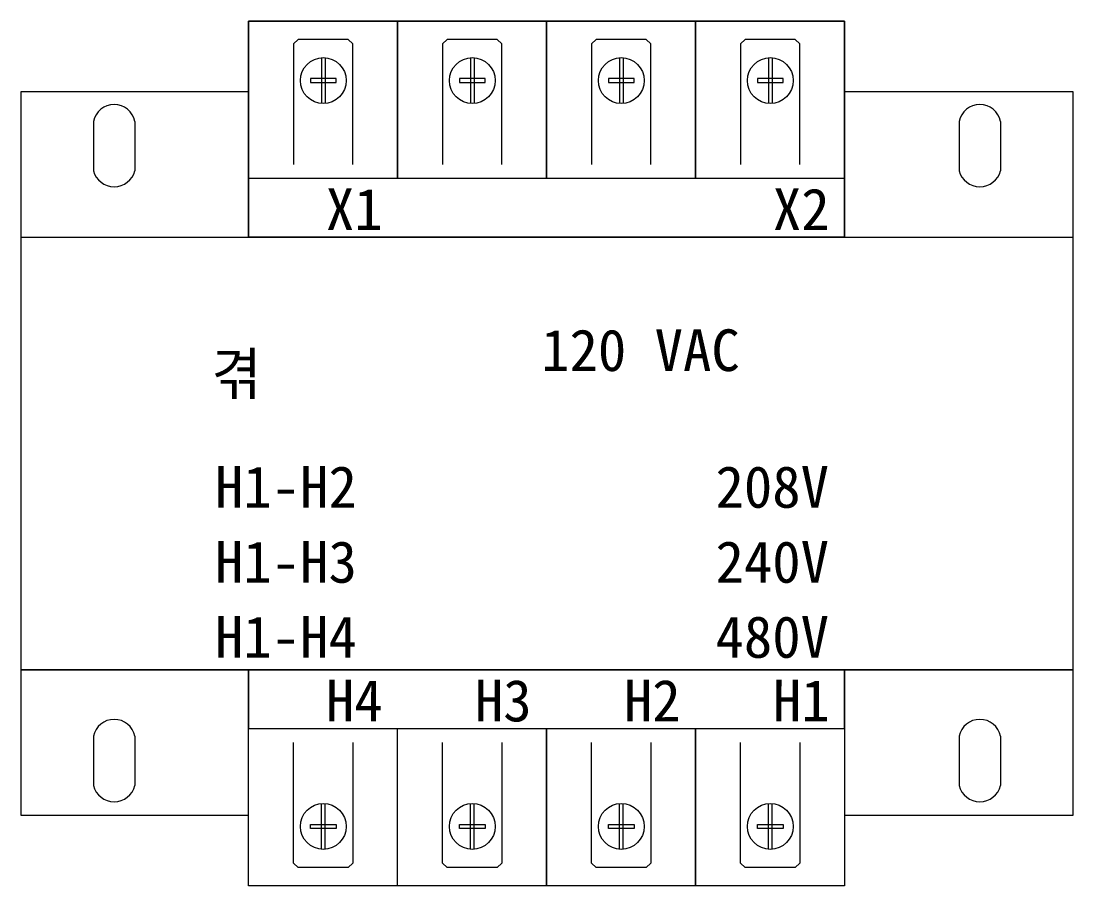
# Model space of a CAD drawing. Extents: x 0 to 0.588, y -0.039 to 0.445.
import ezdxf

# ---------------------------------------------------------------- set-up
doc = ezdxf.new("R2010")
doc.units = 0
doc.layers.add('HS_Dimensions_and_Text', color=7, linetype='Continuous')
doc.layers.add('HS_Electrical_Devices', color=7, linetype='Continuous')

msp = doc.modelspace()

# ---------------------------------------------------------------- linework, layer by layer
at = {"layer": 'HS_Electrical_Devices'}
for p, q in [((0.16802, 0.42434), (0.16802, 0.39877)), ((0.17016, 0.42434), (0.17016, 0.39877)), ((0.25137, 0.42434), (0.25137, 0.39877)), ((0.25352, 0.42434), (0.25352, 0.39877)), ((0.33472, 0.42434), (0.33472, 0.39877)), ((0.33687, 0.42434), (0.33687, 0.39877)), ((0.41807, 0.42434), (0.41807, 0.39877)), ((0.42022, 0.42434), (0.42022, 0.39877)), ((0, 0), (0, 0.40551)), ((0, 0.40551), (0.12729, 0.40551)), ((0.4607, 0.40551), (0.58847, 0.40551)), ((0.58847, 0.40551), (0.58847, 0)), ((0.04047, 0.38865), (0.04047, 0.3611)), ((0.06372, 0.38865), (0.06372, 0.3611)), ((0.52475, 0.38865), (0.52475, 0.3611)), ((0.548, 0.38865), (0.548, 0.3611)), ((0, 0.32382), (0.58847, 0.32382)), ((0, 0.08169), (0.58847, 0.08169)), ((0.04047, 0.04441), (0.04047, 0.01685)), ((0.06372, 0.04441), (0.06372, 0.01685)), ((0.52475, 0.04441), (0.52475, 0.01685)), ((0.548, 0.04441), (0.548, 0.01685)), ((0.16802, -0.01883), (0.16802, 0.00673)), ((0.17016, -0.01883), (0.17016, 0.00673)), ((0.25137, -0.01883), (0.25137, 0.00673)), ((0.25352, -0.01883), (0.25352, 0.00673)), ((0.33472, -0.01883), (0.33472, 0.00673)), ((0.33687, -0.01883), (0.33687, 0.00673)), ((0.41807, -0.01883), (0.41807, 0.00673)), ((0.42022, -0.01883), (0.42022, 0.00673)), ((0.12729, 0), (0, 0)), ((0.58847, 0), (0.4607, 0))]:
    msp.add_line(p, q, dxfattribs=at)
for points in [[(0.12729, 0.32382), (0.12729, 0.44489), (0.4607, 0.44489), (0.4607, 0.32382)], [(0.12729, 0.44489), (0.12729, 0.32382), (0.4607, 0.32382), (0.4607, 0.44489)], [(0.17628, 0.41263), (0.16189, 0.41263), (0.16189, 0.41048), (0.17628, 0.41048)], [(0.25964, 0.41263), (0.24525, 0.41263), (0.24525, 0.41048), (0.25964, 0.41048)], [(0.34299, 0.41263), (0.3286, 0.41263), (0.3286, 0.41048), (0.34299, 0.41048)], [(0.42634, 0.41263), (0.41195, 0.41263), (0.41195, 0.41048), (0.42634, 0.41048)], [(0.12729, 0.35677), (0.12729, 0.32382), (0.4607, 0.32382), (0.4607, 0.35677)], [(0, 0.32382), (0.58847, 0.32382), (0.58847, 0.08169), (0, 0.08169)], [(0.12729, -0.03938), (0.12729, 0.08169), (0.4607, 0.08169), (0.4607, -0.03938)], [(0.12729, -0.03938), (0.12729, 0.08169), (0.4607, 0.08169), (0.4607, -0.03938)], [(0.12729, 0.08169), (0.12729, 0.04874), (0.4607, 0.04874), (0.4607, 0.08169)], [(0.17628, -0.00712), (0.16189, -0.00712), (0.16189, -0.00497), (0.17628, -0.00497)], [(0.25964, -0.00712), (0.24525, -0.00712), (0.24525, -0.00497), (0.25964, -0.00497)], [(0.34299, -0.00712), (0.3286, -0.00712), (0.3286, -0.00497), (0.34299, -0.00497)], [(0.42634, -0.00712), (0.41195, -0.00712), (0.41195, -0.00497), (0.42634, -0.00497)]]:
    msp.add_lwpolyline(points, close=True, dxfattribs=at)
for points in [[(0.21064, 0.32382), (0.12729, 0.32382), (0.12729, 0.44489), (0.21064, 0.44489), (0.21064, 0.35677)], [(0.21064, 0.35677), (0.21064, 0.44489), (0.29399, 0.44489), (0.29399, 0.35677)], [(0.29399, 0.35677), (0.29399, 0.44489), (0.37735, 0.44489), (0.37735, 0.35677)], [(0.37735, 0.35677), (0.37735, 0.44489), (0.4607, 0.44489), (0.4607, 0.32382), (0.37735, 0.32382)], [(0.18554, 0.3646), (0.18554, 0.43203), (0.18296, 0.43461), (0.15497, 0.43461), (0.15239, 0.43203), (0.15239, 0.3646)], [(0.26889, 0.3646), (0.26889, 0.43203), (0.26631, 0.43461), (0.23833, 0.43461), (0.23574, 0.43203), (0.23574, 0.3646)], [(0.35225, 0.3646), (0.35225, 0.43203), (0.34966, 0.43461), (0.32168, 0.43461), (0.3191, 0.43203), (0.3191, 0.3646)], [(0.4356, 0.3646), (0.4356, 0.43203), (0.43302, 0.43461), (0.40503, 0.43461), (0.40245, 0.43203), (0.40245, 0.3646)], [(0.29399, 0.32382), (0.21064, 0.32382)], [(0.37735, 0.32382), (0.29399, 0.32382)], [(0.21064, 0.08169), (0.29399, 0.08169)], [(0.29399, 0.08169), (0.37735, 0.08169)], [(0.37735, 0.08169), (0.4607, 0.08169), (0.4607, -0.03938), (0.37735, -0.03938), (0.37735, 0.04874)], [(0.29399, 0.04874), (0.29399, -0.03938), (0.21064, -0.03938), (0.21064, 0.04874)], [(0.37735, 0.04874), (0.37735, -0.03938), (0.29399, -0.03938), (0.29399, 0.04874)], [(0.18554, 0.04091), (0.18554, -0.02652), (0.18296, -0.02911), (0.15497, -0.02911), (0.15239, -0.02652), (0.15239, 0.04091)], [(0.26889, 0.04091), (0.26889, -0.02652), (0.26631, -0.02911), (0.23833, -0.02911), (0.23574, -0.02652), (0.23574, 0.04091)], [(0.35225, 0.04091), (0.35225, -0.02652), (0.34966, -0.02911), (0.32168, -0.02911), (0.3191, -0.02652), (0.3191, 0.04091)], [(0.4356, 0.04091), (0.4356, -0.02652), (0.43302, -0.02911), (0.40503, -0.02911), (0.40245, -0.02652), (0.40245, 0.04091)]]:
    msp.add_lwpolyline(points, dxfattribs=at)
for centre in [(0.16909, 0.41156), (0.25244, 0.41156), (0.33579, 0.41156), (0.41915, 0.41156), (0.16909, -0.00605), (0.25244, -0.00605), (0.33579, -0.00605), (0.41915, -0.00605)]:
    msp.add_circle(centre, 0.01283, dxfattribs=at)
for centre, radius, start, end in [((0.0521, 0.38626), 0.01187, 11.64059, 168.35941), ((0.53637, 0.38626), 0.01187, 11.64059, 168.35941), ((0.0521, 0.36405), 0.01199, 194.23753, 345.76247), ((0.53637, 0.36405), 0.01199, 194.23753, 345.76247), ((0.0521, 0.04201), 0.01187, 11.64059, 168.35941), ((0.53637, 0.04201), 0.01187, 11.64059, 168.35941), ((0.0521, 0.0198), 0.01199, 194.23753, 345.76247), ((0.53637, 0.0198), 0.01199, 194.23753, 345.76247)]:
    msp.add_arc(centre, radius, start, end, dxfattribs=at)

# ---------------------------------------------------------------- texts
at = {"layer": 'HS_Dimensions_and_Text'}
for s, p in [('X1', (0.17053, 0.32784)), ('X2', (0.42059, 0.32784)), ('120 VAC', (0.29096, 0.24894)), ('H4', (0.17053, 0.05276)), ('H3', (0.25388, 0.05276)), ('H2', (0.33724, 0.05276)), ('H1', (0.42059, 0.05276))]:
    msp.add_text(s, height=0.023333, rotation=359.99044, dxfattribs=at).set_placement(p)
for s, height, p in [('겪', 0.02333, (0.10656, 0.2357)), ('H1-H2', 0.023333, (0.10851, 0.17239)), ('208V', 0.023333, (0.38851, 0.17239)), ('H1-H3', 0.023333, (0.10851, 0.13039)), ('240V', 0.023333, (0.38851, 0.13039)), ('H1-H4', 0.023333, (0.10851, 0.08839)), ('480V', 0.023333, (0.38851, 0.08839))]:
    msp.add_text(s, height=height, dxfattribs=at).set_placement(p)

doc.saveas('drawing.dxf')
